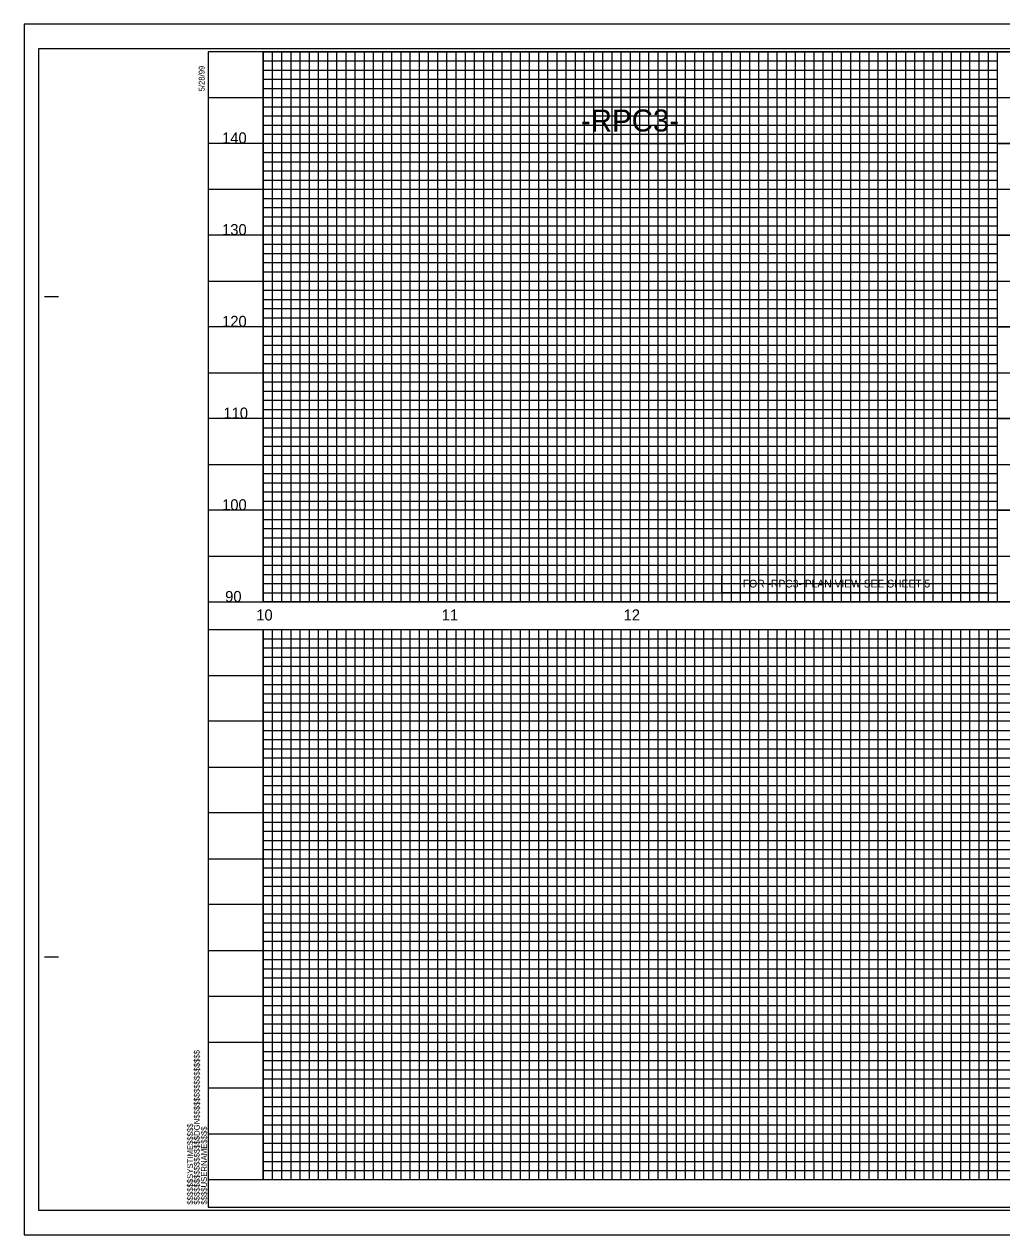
# Model space of a CAD drawing. Extents: x -130 to 890, y -29895 to -29235.
# Drawn here: x -130 to 403, y -29895 to -29235 of the extents above; entities that cross this region are included whole.
import ezdxf

# ---------------------------------------------------------------- set-up
doc = ezdxf.new("R2010")
doc.units = 0
for name, color, linetype in [('Exist Vertical Profile Horizontal Axis Label Major', 7, 'Continuous'), ('Exist Vertical Profile Vertical Axis Label', 7, 'Continuous'), ('Prop Grid Mask', 7, 'Continuous'), ('Prop PFL Text', 7, 'Continuous'), ('Scratch_Level_0', 7, 'Continuous'), ('Sheet Cutting Line CELL', 7, 'Continuous'), ('Sheet Layout Profile Border Port 1', 7, 'Continuous'), ('Sheet Layout Profile Border Port 2', 7, 'Continuous'), ('Sheet Plot Border Inside CELL', 7, 'Continuous'), ('Sheet Plot Border Outside CELL', 7, 'Continuous'), ('Sheet Profile CELL', 7, 'Continuous'), ('Sheet Profile Grid Major CELL', 7, 'Continuous'), ('Sheet Profile Grid Middle CELL', 7, 'Continuous'), ('Sheet Profile Grid Minor CELL', 7, 'Continuous')]:
    doc.layers.add(name, color=color, linetype=linetype)

msp = doc.modelspace()

# ---------------------------------------------------------------- linework, layer by layer
at = {"layer": 'Exist Vertical Profile Vertical Axis Label'}
msp.add_lwpolyline([(250, -29534.75), (395, -29534.75), (395, -29544.75), (250, -29544.75)], close=True, dxfattribs=at)
at = {"layer": 'Prop Grid Mask'}
for points in [[(170, -29299.75), (230, -29299.75), (230, -29274.75), (170, -29274.75)], [(250, -29534.75), (395, -29534.75), (395, -29544.75), (250, -29544.75)]]:
    msp.add_lwpolyline(points, close=True, dxfattribs=at)
at = {"layer": 'Prop PFL Text'}
msp.add_lwpolyline([(170, -29299.75), (230, -29299.75), (230, -29274.75), (170, -29274.75)], close=True, dxfattribs=at)
at = {"layer": 'Scratch_Level_0'}
msp.add_lwpolyline([(0, -29249.75), (400, -29249.75), (400, -29549.75), (0, -29549.75)], close=True, dxfattribs=at)
at = {"layer": 'Sheet Cutting Line CELL'}
for p, q in [((889.8, -29234.75), (-130.2, -29234.75)), ((-130.2, -29234.75), (-130.2, -29894.75)), ((-130.2, -29894.75), (889.8, -29894.75))]:
    msp.add_line(p, q, dxfattribs=at)
at = {"layer": 'Sheet Layout Profile Border Port 1'}
msp.add_lwpolyline([(0, -29249.75), (749.97, -29249.75), (749.97, -29369.63), (840, -29369.75), (840, -29549.75), (0, -29549.75)], close=True, dxfattribs=at)
at = {"layer": 'Sheet Layout Profile Border Port 2'}
msp.add_lwpolyline([(0, -29564.75), (840, -29564.75), (840, -29864.75), (0, -29864.75)], close=True, dxfattribs=at)
at = {"layer": 'Sheet Plot Border Inside CELL'}
msp.add_lwpolyline([(-122.4, -29881.28), (877.5, -29881.28), (877.5, -29248.22), (-122.4, -29248.22)], close=True, dxfattribs=at)
at = {"layer": 'Sheet Plot Border Outside CELL'}
msp.add_lwpolyline([(-130.2, -29894.75), (889.8, -29894.75), (889.8, -29234.75), (-130.2, -29234.75)], close=True, dxfattribs=at)
at = {"layer": 'Sheet Profile CELL'}
for p, q in [((-119.1, -29383.25), (-111.6, -29383.25)), ((-30, -29549.75), (870, -29549.75)), ((-30, -29564.75), (870, -29564.75)), ((-119.1, -29743.25), (-111.6, -29743.25)), ((870, -29864.75), (-30, -29864.75)), ((-30, -29879.75), (870, -29879.75)), ((-30, -29879.75), (-30, -29879.75)), ((-30, -29879.75), (-30, -29879.75)), ((-30, -29879.75), (-30, -29879.75)), ((-30, -29879.75), (-30, -29879.75)), ((-30, -29879.75), (-30, -29879.75)), ((-30, -29879.75), (-30, -29879.75)), ((-30, -29879.75), (-30, -29879.75))]:
    msp.add_line(p, q, dxfattribs=at)
msp.add_lwpolyline([(870, -29249.75), (-30, -29249.75), (-30, -29879.75), (870, -29879.75)], close=True, dxfattribs=at)
msp.add_lwpolyline([(-7.5, -29879.75), (-7.5, -29879.75)], dxfattribs=at)
at = {"layer": 'Sheet Profile Grid Major CELL'}
for p, q in [((0, -29249.75), (0, -29549.75)), ((25, -29249.75), (25, -29549.75)), ((50, -29249.75), (50, -29549.75)), ((75, -29249.75), (75, -29549.75)), ((100, -29249.75), (100, -29549.75)), ((125, -29249.75), (125, -29549.75)), ((150, -29249.75), (150, -29549.75)), ((175, -29249.75), (175, -29549.75)), ((200, -29249.75), (200, -29549.75)), ((225, -29249.75), (225, -29549.75)), ((250, -29249.75), (250, -29549.75)), ((275, -29249.75), (275, -29549.75)), ((300, -29249.75), (300, -29549.75)), ((325, -29249.75), (325, -29549.75)), ((350, -29249.75), (350, -29549.75)), ((375, -29249.75), (375, -29549.75)), ((400, -29249.75), (400, -29549.75)), ((-30, -29274.75), (750, -29274.75)), ((400, -29274.75), (450, -29274.75)), ((750, -29299.75), (-30, -29299.75)), ((400, -29299.75), (450, -29299.75)), ((-30, -29324.75), (750, -29324.75)), ((400, -29324.75), (450, -29324.75)), ((750, -29349.75), (-30, -29349.75)), ((400, -29349.75), (450, -29349.75)), ((-30, -29374.75), (870, -29374.75)), ((400, -29374.75), (450, -29374.75)), ((870, -29399.75), (-30, -29399.75)), ((400, -29399.75), (450, -29399.75)), ((-30, -29424.75), (870, -29424.75)), ((400, -29424.75), (450, -29424.75)), ((870, -29449.75), (-30, -29449.75)), ((400, -29449.75), (450, -29449.75)), ((-30, -29474.75), (870, -29474.75)), ((400, -29474.75), (450, -29474.75)), ((870, -29499.75), (-30, -29499.75)), ((400, -29499.75), (450, -29499.75)), ((-30, -29524.75), (870, -29524.75)), ((400, -29524.75), (449.91, -29524.75)), ((0, -29564.75), (0, -29864.75)), ((25, -29564.75), (25, -29864.75)), ((50, -29564.75), (50, -29864.75)), ((75, -29564.75), (75, -29864.75)), ((100, -29564.75), (100, -29864.75)), ((125, -29564.75), (125, -29864.75)), ((150, -29564.75), (150, -29864.75)), ((175, -29564.75), (175, -29864.75)), ((200, -29564.75), (200, -29864.75)), ((225, -29564.75), (225, -29864.75)), ((250, -29564.75), (250, -29864.75)), ((275, -29564.75), (275, -29864.75)), ((300, -29564.75), (300, -29864.75)), ((325, -29564.75), (325, -29864.75)), ((350, -29564.75), (350, -29864.75)), ((375, -29564.75), (375, -29864.75)), ((400, -29564.75), (400, -29864.75)), ((-30, -29589.75), (870, -29589.75)), ((870, -29614.75), (-30, -29614.75)), ((-30, -29639.75), (870, -29639.75)), ((870, -29664.75), (-30, -29664.75)), ((-30, -29689.75), (870, -29689.75)), ((870, -29714.75), (-30, -29714.75)), ((-30, -29739.75), (870, -29739.75)), ((870, -29764.75), (-30, -29764.75)), ((-30, -29789.75), (870, -29789.75)), ((870, -29814.75), (-30, -29814.75)), ((-30, -29839.75), (870, -29839.75))]:
    msp.add_line(p, q, dxfattribs=at)
at = {"layer": 'Sheet Profile Grid Middle CELL'}
for p, q in [((0, -29254.75), (400, -29254.75)), ((0, -29259.75), (400, -29259.75)), ((0, -29264.75), (400, -29264.75)), ((0, -29269.75), (400, -29269.75)), ((0, -29279.75), (400, -29279.75)), ((0, -29284.75), (400, -29284.75)), ((0, -29289.75), (400, -29289.75)), ((0, -29294.75), (400, -29294.75)), ((0, -29304.75), (400, -29304.75)), ((0, -29309.75), (400, -29309.75)), ((0, -29314.75), (400, -29314.75)), ((0, -29319.75), (400, -29319.75)), ((0, -29329.75), (400, -29329.75)), ((0, -29334.75), (400, -29334.75)), ((0, -29339.75), (400, -29339.75)), ((0, -29344.75), (400, -29344.75)), ((0, -29354.75), (400, -29354.75)), ((0, -29359.75), (400, -29359.75)), ((0, -29364.75), (400, -29364.75)), ((0, -29369.75), (400, -29369.75)), ((0, -29379.75), (400, -29379.75)), ((0, -29384.75), (400, -29384.75)), ((0, -29389.75), (400, -29389.75)), ((0, -29394.75), (400, -29394.75)), ((0, -29404.75), (400, -29404.75)), ((0, -29409.75), (400, -29409.75)), ((0, -29414.75), (400, -29414.75)), ((0, -29419.75), (400, -29419.75)), ((0, -29429.75), (400, -29429.75)), ((0, -29434.75), (400, -29434.75)), ((0, -29439.75), (400, -29439.75)), ((0, -29444.75), (400, -29444.75)), ((0, -29454.75), (400, -29454.75)), ((0, -29459.75), (400, -29459.75)), ((0, -29464.75), (400, -29464.75)), ((0, -29469.75), (400, -29469.75)), ((0, -29479.75), (400, -29479.75)), ((0, -29484.75), (400, -29484.75)), ((0, -29489.75), (400, -29489.75)), ((0, -29494.75), (400, -29494.75)), ((0, -29504.75), (400, -29504.75)), ((0, -29509.75), (400, -29509.75)), ((0, -29514.75), (400, -29514.75)), ((0, -29519.75), (400, -29519.75)), ((0, -29529.75), (400, -29529.75)), ((0, -29534.75), (400, -29534.75)), ((0, -29539.75), (400, -29539.75)), ((0, -29544.75), (400, -29544.75)), ((0, -29569.75), (840, -29569.75)), ((0, -29574.75), (840, -29574.75)), ((0, -29579.75), (840, -29579.75)), ((0, -29584.75), (840, -29584.75)), ((0, -29594.75), (840, -29594.75)), ((0, -29599.75), (840, -29599.75)), ((0, -29604.75), (840, -29604.75)), ((0, -29609.75), (840, -29609.75)), ((0, -29619.75), (840, -29619.75)), ((0, -29624.75), (840, -29624.75)), ((0, -29629.75), (840, -29629.75)), ((0, -29634.75), (840, -29634.75)), ((0, -29644.75), (840, -29644.75)), ((0, -29649.75), (840, -29649.75)), ((0, -29654.75), (840, -29654.75)), ((0, -29659.75), (840, -29659.75)), ((0, -29669.75), (840, -29669.75)), ((0, -29674.75), (840, -29674.75)), ((0, -29679.75), (840, -29679.75)), ((0, -29684.75), (840, -29684.75)), ((0, -29694.75), (840, -29694.75)), ((0, -29699.75), (840, -29699.75)), ((0, -29704.75), (840, -29704.75)), ((0, -29709.75), (840, -29709.75)), ((0, -29719.75), (840, -29719.75)), ((0, -29724.75), (840, -29724.75)), ((0, -29729.75), (840, -29729.75)), ((0, -29734.75), (840, -29734.75)), ((0, -29744.75), (840, -29744.75)), ((0, -29749.75), (840, -29749.75)), ((0, -29754.75), (840, -29754.75)), ((0, -29759.75), (840, -29759.75)), ((0, -29769.75), (840, -29769.75)), ((0, -29774.75), (840, -29774.75)), ((0, -29779.75), (840, -29779.75)), ((0, -29784.75), (840, -29784.75)), ((0, -29794.75), (840, -29794.75)), ((0, -29799.75), (840, -29799.75)), ((0, -29804.75), (840, -29804.75)), ((0, -29809.75), (840, -29809.75)), ((0, -29819.75), (840, -29819.75)), ((0, -29824.75), (840, -29824.75)), ((0, -29829.75), (840, -29829.75)), ((0, -29834.75), (840, -29834.75)), ((0, -29844.75), (840, -29844.75)), ((0, -29849.75), (840, -29849.75)), ((0, -29854.75), (840, -29854.75)), ((0, -29859.75), (840, -29859.75))]:
    msp.add_line(p, q, dxfattribs=at)
at = {"layer": 'Sheet Profile Grid Minor CELL'}
for p, q in [((5, -29249.75), (5, -29549.75)), ((10, -29249.75), (10, -29549.75)), ((15, -29249.75), (15, -29549.75)), ((20, -29249.75), (20, -29549.75)), ((30, -29249.75), (30, -29549.75)), ((35, -29249.75), (35, -29549.75)), ((40, -29249.75), (40, -29549.75)), ((45, -29249.75), (45, -29549.75)), ((55, -29249.75), (55, -29549.75)), ((60, -29249.75), (60, -29549.75)), ((65, -29249.75), (65, -29549.75)), ((70, -29249.75), (70, -29549.75)), ((80, -29249.75), (80, -29549.75)), ((85, -29249.75), (85, -29549.75)), ((90, -29249.75), (90, -29549.75)), ((95, -29249.75), (95, -29549.75)), ((105, -29249.75), (105, -29549.75)), ((110, -29249.75), (110, -29549.75)), ((115, -29249.75), (115, -29549.75)), ((120, -29249.75), (120, -29549.75)), ((130, -29249.75), (130, -29549.75)), ((135, -29249.75), (135, -29549.75)), ((140, -29249.75), (140, -29549.75)), ((145, -29249.75), (145, -29549.75)), ((155, -29249.75), (155, -29549.75)), ((160, -29249.75), (160, -29549.75)), ((165, -29249.75), (165, -29549.75)), ((170, -29249.75), (170, -29549.75)), ((180, -29249.75), (180, -29549.75)), ((185, -29249.75), (185, -29549.75)), ((190, -29249.75), (190, -29549.75)), ((195, -29249.75), (195, -29549.75)), ((205, -29249.75), (205, -29549.75)), ((210, -29249.75), (210, -29549.75)), ((215, -29249.75), (215, -29549.75)), ((220, -29249.75), (220, -29549.75)), ((230, -29249.75), (230, -29549.75)), ((235, -29249.75), (235, -29549.75)), ((240, -29249.75), (240, -29549.75)), ((245, -29249.75), (245, -29549.75)), ((255, -29249.75), (255, -29549.75)), ((260, -29249.75), (260, -29549.75)), ((265, -29249.75), (265, -29549.75)), ((270, -29249.75), (270, -29549.75)), ((280, -29249.75), (280, -29549.75)), ((285, -29249.75), (285, -29549.75)), ((290, -29249.75), (290, -29549.75)), ((295, -29249.75), (295, -29549.75)), ((305, -29249.75), (305, -29549.75)), ((310, -29249.75), (310, -29549.75)), ((315, -29249.75), (315, -29549.75)), ((320, -29249.75), (320, -29549.75)), ((330, -29249.75), (330, -29549.75)), ((335, -29249.75), (335, -29549.75)), ((340, -29249.75), (340, -29549.75)), ((345, -29249.75), (345, -29549.75)), ((355, -29249.75), (355, -29549.75)), ((360, -29249.75), (360, -29549.75)), ((365, -29249.75), (365, -29549.75)), ((370, -29249.75), (370, -29549.75)), ((380, -29249.75), (380, -29549.75)), ((385, -29249.75), (385, -29549.75)), ((390, -29249.75), (390, -29549.75)), ((395, -29249.75), (395, -29549.75)), ((0, -29255.75), (0, -29255.75)), ((5, -29564.75), (5, -29864.75)), ((10, -29564.75), (10, -29864.75)), ((15, -29564.75), (15, -29864.75)), ((20, -29564.75), (20, -29864.75)), ((30, -29564.75), (30, -29864.75)), ((35, -29564.75), (35, -29864.75)), ((40, -29564.75), (40, -29864.75)), ((45, -29564.75), (45, -29864.75)), ((55, -29564.75), (55, -29864.75)), ((60, -29564.75), (60, -29864.75)), ((65, -29564.75), (65, -29864.75)), ((70, -29564.75), (70, -29864.75)), ((80, -29564.75), (80, -29864.75)), ((85, -29564.75), (85, -29864.75)), ((90, -29564.75), (90, -29864.75)), ((95, -29564.75), (95, -29864.75)), ((105, -29564.75), (105, -29864.75)), ((110, -29564.75), (110, -29864.75)), ((115, -29564.75), (115, -29864.75)), ((120, -29564.75), (120, -29864.75)), ((130, -29564.75), (130, -29864.75)), ((135, -29564.75), (135, -29864.75)), ((140, -29564.75), (140, -29864.75)), ((145, -29564.75), (145, -29864.75)), ((155, -29564.75), (155, -29864.75)), ((160, -29564.75), (160, -29864.75)), ((165, -29564.75), (165, -29864.75)), ((170, -29564.75), (170, -29864.75)), ((180, -29564.75), (180, -29864.75)), ((185, -29564.75), (185, -29864.75)), ((190, -29564.75), (190, -29864.75)), ((195, -29564.75), (195, -29864.75)), ((205, -29564.75), (205, -29864.75)), ((210, -29564.75), (210, -29864.75)), ((215, -29564.75), (215, -29864.75)), ((220, -29564.75), (220, -29864.75)), ((230, -29564.75), (230, -29864.75)), ((235, -29564.75), (235, -29864.75)), ((240, -29564.75), (240, -29864.75)), ((245, -29564.75), (245, -29864.75)), ((255, -29564.75), (255, -29864.75)), ((260, -29564.75), (260, -29864.75)), ((265, -29564.75), (265, -29864.75)), ((270, -29564.75), (270, -29864.75)), ((280, -29564.75), (280, -29864.75)), ((285, -29564.75), (285, -29864.75)), ((290, -29564.75), (290, -29864.75)), ((295, -29564.75), (295, -29864.75)), ((305, -29564.75), (305, -29864.75)), ((310, -29564.75), (310, -29864.75)), ((315, -29564.75), (315, -29864.75)), ((320, -29564.75), (320, -29864.75)), ((330, -29564.75), (330, -29864.75)), ((335, -29564.75), (335, -29864.75)), ((340, -29564.75), (340, -29864.75)), ((345, -29564.75), (345, -29864.75)), ((355, -29564.75), (355, -29864.75)), ((360, -29564.75), (360, -29864.75)), ((365, -29564.75), (365, -29864.75)), ((370, -29564.75), (370, -29864.75)), ((380, -29564.75), (380, -29864.75)), ((385, -29564.75), (385, -29864.75)), ((390, -29564.75), (390, -29864.75)), ((395, -29564.75), (395, -29864.75)), ((0, -29570.75), (0, -29570.75))]:
    msp.add_line(p, q, dxfattribs=at)

# ---------------------------------------------------------------- texts
at = {"layer": 'Exist Vertical Profile Horizontal Axis Label Major'}
for s, p in [('10', (-3.73, -29559.81)), ('11', (97.32, -29559.81)), ('12', (196.44, -29559.81))]:
    msp.add_text(s, height=6, dxfattribs=at).set_placement(p)
at = {"layer": 'Exist Vertical Profile Vertical Axis Label'}
for s, p in [('140', (-22.36, -29299.75)), ('130', (-22.36, -29349.75)), ('120', (-22.36, -29399.75)), ('110', (-21.64, -29449.75)), ('100', (-22.36, -29499.75)), ('90', (-20.71, -29549.75))]:
    msp.add_text(s, height=6, dxfattribs=at).set_placement(p)
at = {"layer": 'Prop PFL Text'}
for s, height, p in [('-RPC3-', 12, (173.18, -29293.25)), ('FOR -RPC3- PLAN VIEW SEE SHEET 5', 4.2, (261.44, -29541.85))]:
    msp.add_text(s, height=height, dxfattribs=at).set_placement(p)
at = {"layer": 'Sheet Profile CELL'}
for s, p in [('5/28/99', (-31.94, -29271.4)), ('$$$$$$$$$$$$$$$$DGN$$$$$$$$$$$$$$$$', (-34.58, -29878.33)), ('$$$$$$SYSTIME$$$$$', (-38.21, -29878.33)), ('$$$$USERNAME$$$$', (-30.64, -29878.32))]:
    msp.add_text(s, height=3.15, rotation=90, dxfattribs=at).set_placement(p)

doc.saveas('drawing.dxf')
